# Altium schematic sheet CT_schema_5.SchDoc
size 255 x 245 mm
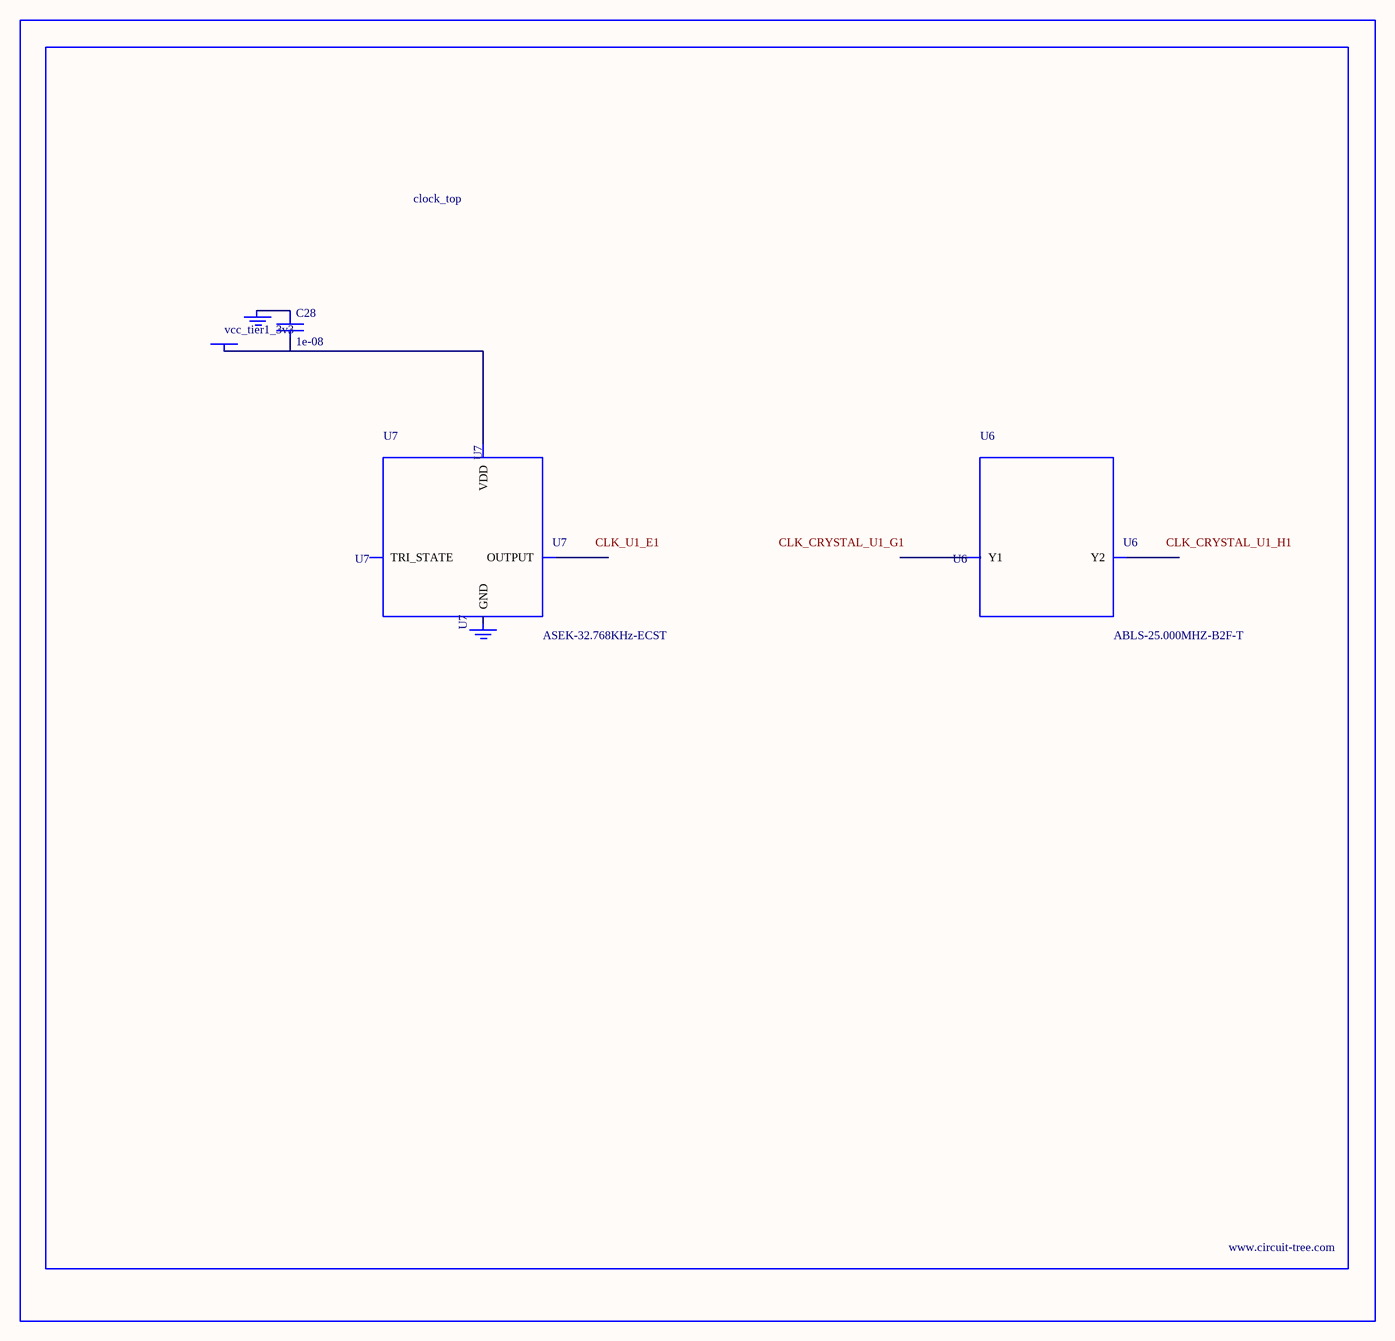
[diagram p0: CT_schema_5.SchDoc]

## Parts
BORDER4  (no value)
C28  1e-08  [C0402]
GND_INSTANCE_4_0  (no value)
GND_INSTANCE_4_1  (no value)
POWER_INSTANCE_4_0  vcc_tier1_3v3
U6  ABLS-25.000MHZ-B2F-T  [ABLS-25.000MHZ-B2F-T]
U7  ASEK-32.768KHz-ECST  [ASEK]

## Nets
NetC28_1: C28.1 GND_INSTANCE_4_0.0(GND)
NetC28_2: C28.2 POWER_INSTANCE_4_0.0(PWR) U7.4(VDD)

Not connected (* = marked no-connect by the designer): GND_INSTANCE_4_1 0(GND); U6 1(Y1) 2(Y2); U7 1(TRI_STATE) 2(GND) 3(OUTPUT)

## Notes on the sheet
- Labels drawn without touching a wire or pin: CLK_CRYSTAL_U1_G1, CLK_CRYSTAL_U1_H1, CLK_U1_E1

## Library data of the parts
BORDER4 = BORDER_PAGE4
C28 = C0402C103K3RAC
GND_INSTANCE_4_0 GND_INSTANCE_4_1 = GND
POWER_INSTANCE_4_0 = PWR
